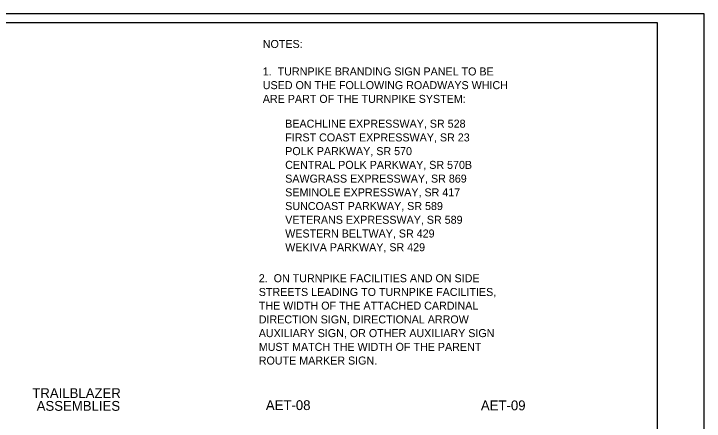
# Model space of a CAD drawing. Extents: x 17890587 to 17890754, y 17897693 to 17897992.
# Drawn here: x 17890611.5 to 17890635.17, y 17897890.24 to 17897904.2 of the extents above; entities that cross this region are included whole.
import ezdxf

# ---------------------------------------------------------------- set-up
doc = ezdxf.new("R2010")
doc.units = 0
for name, color, linetype in [('PlotBorder_dp', 7, 'Continuous'), ('SheetBorder_dp', 7, 'Continuous'), ('TextMisc', 7, 'Continuous')]:
    doc.layers.add(name, color=color, linetype=linetype)

msp = doc.modelspace()

# ---------------------------------------------------------------- linework, layer by layer
at = {"layer": 'PlotBorder_dp'}
msp.add_lwpolyline([(17890586.756, 17897873.104), (17890635.165, 17897873.104), (17890635.165, 17897904.203), (17890586.756, 17897904.203)], close=True, dxfattribs=at)
at = {"layer": 'SheetBorder_dp'}
for p, q in [((17890588.37, 17897903.909), (17890633.551, 17897903.909)), ((17890633.551, 17897903.909), (17890633.551, 17897873.397))]:
    msp.add_line(p, q, dxfattribs=at)

# ---------------------------------------------------------------- texts
at = {"layer": 'TextMisc'}
for s, height, p in [('NOTES:', 0.2745, (17890620.037, 17897903.031)), ('1.  TURNPIKE BRANDING SIGN PANEL TO BE ', 0.27448, (17890620.037, 17897902.09)), ('USED ON THE FOLLOWING ROADWAYS WHICH ', 0.27448, (17890620.037, 17897901.62)), ('ARE PART OF THE TURNPIKE SYSTEM:', 0.27448, (17890620.037, 17897901.149)), ('BEACHLINE EXPRESSWAY, SR 528', 0.27448, (17890620.805, 17897900.299)), ('FIRST COAST EXPRESSWAY, SR 23', 0.27448, (17890620.805, 17897899.828)), ('POLK PARKWAY, SR 570', 0.27448, (17890620.805, 17897899.358)), ('CENTRAL POLK PARKWAY, SR 570B', 0.27448, (17890620.805, 17897898.887)), ('SAWGRASS EXPRESSWAY, SR 869', 0.27448, (17890620.805, 17897898.416)), ('SEMINOLE EXPRESSWAY, SR 417', 0.27448, (17890620.805, 17897897.946)), ('SUNCOAST PARKWAY, SR 589', 0.27448, (17890620.805, 17897897.475)), ('VETERANS EXPRESSWAY, SR 589', 0.27448, (17890620.805, 17897897.005)), ('WESTERN BELTWAY, SR 429', 0.27448, (17890620.805, 17897896.534)), ('WEKIVA PARKWAY, SR 429', 0.27448, (17890620.805, 17897896.064)), ('2.  ON TURNPIKE FACILITIES AND ON SIDE ', 0.27448, (17890619.899, 17897895.001)), ('STREETS LEADING TO TURNPIKE FACILITIES, ', 0.27448, (17890619.899, 17897894.53)), ('THE WIDTH OF THE ATTACHED CARDINAL ', 0.27448, (17890619.899, 17897894.06)), ('DIRECTION SIGN, DIRECTIONAL ARROW ', 0.27448, (17890619.899, 17897893.589)), ('AUXILIARY SIGN, OR OTHER AUXILIARY SIGN ', 0.27448, (17890619.899, 17897893.119)), ('MUST MATCH THE WIDTH OF THE PARENT ', 0.27448, (17890619.899, 17897892.648)), ('ROUTE MARKER SIGN.', 0.27448, (17890619.899, 17897892.178)), ('TRAILBLAZER', 0.33745, (17890612.137, 17897891.031)), ('ASSEMBLIES', 0.3375, (17890612.287, 17897890.593)), ('AET-08', 0.3375, (17890620.142, 17897890.618)), ('AET-09', 0.3375, (17890627.512, 17897890.61))]:
    msp.add_text(s, height=height, dxfattribs=at).set_placement(p)

doc.saveas('drawing.dxf')
